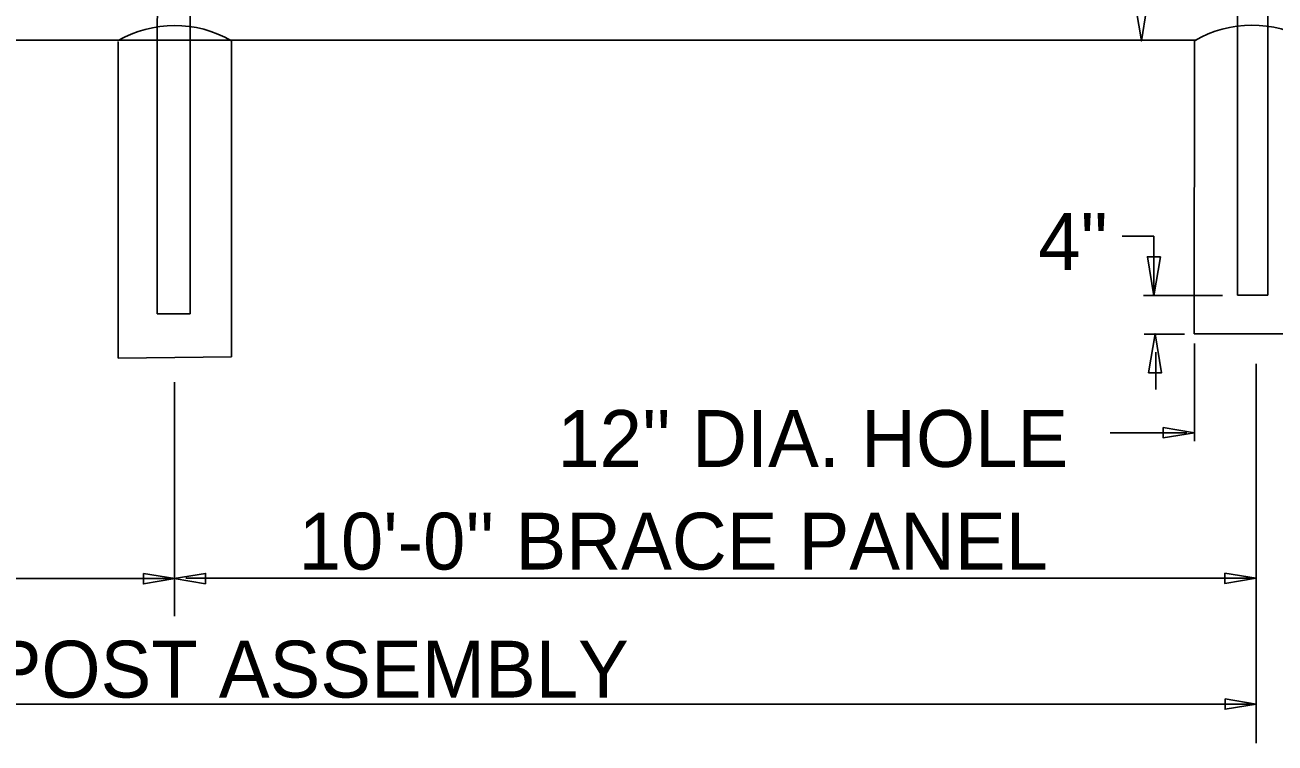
# Model space of a CAD drawing. Extents: x 0 to 2.85, y -0.1 to 1.83.
# Drawn here: x 1.2785 to 1.4984, y 1.158 to 1.2843 of the extents above; entities that cross this region are included whole.
import ezdxf

# ---------------------------------------------------------------- set-up
doc = ezdxf.new("R2010")
doc.units = 0
for name, color, linetype in [('CT_CSHT_GeneralLabel', 7, 'Continuous'), ('CT_Dimensions', 7, 'Continuous'), ('sb_Chainlink Fence', 7, 'Continuous'), ('sb_Earth', 7, 'Continuous'), ('sb_Existing Concrete', 7, 'Continuous'), ('sb_Existing Structural Steel', 7, 'Continuous')]:
    doc.layers.add(name, color=color, linetype=linetype)

msp = doc.modelspace()

# ---------------------------------------------------------------- linework, layer by layer
at = {"layer": 'CT_Dimensions'}
for p, q in [((1.4714931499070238, 1.247114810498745), (1.4771040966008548, 1.247114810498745)), ((1.4771040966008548, 1.2366632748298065), (1.4771040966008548, 1.247114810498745)), ((1.4752588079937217, 1.2366906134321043), (1.4891635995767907, 1.2366906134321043)), ((1.4842187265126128, 1.2110793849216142), (1.4842187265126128, 1.2282577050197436)), ((1.477443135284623, 1.2201522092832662), (1.477443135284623, 1.2267055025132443)), ((1.495061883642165, 1.1579610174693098), (1.495061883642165, 1.2246650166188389)), ((1.3048382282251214, 1.1803051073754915), (1.3048382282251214, 1.2214341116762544)), ((1.4693816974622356, 1.212532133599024), (1.4829063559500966, 1.212532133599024)), ((1.495061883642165, 1.1605798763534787), (1.495061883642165, 1.1919560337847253)), ((1.1104326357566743, 1.1868854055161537), (1.3047967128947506, 1.1868854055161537)), ((1.306856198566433, 1.1869481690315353), (1.495061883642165, 1.1869481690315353)), ((1.1146954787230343, 1.1648183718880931), (1.4947073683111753, 1.1648183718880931))]:
    msp.add_line(p, q, dxfattribs=at)
for points in [[(1.475816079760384, 1.287000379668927), (1.4748999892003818, 1.2815038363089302), (1.4739838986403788, 1.287000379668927)], [(1.4782458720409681, 1.2435038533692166), (1.4771026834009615, 1.2366447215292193), (1.4759594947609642, 1.2435038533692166)], [(1.4761670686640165, 1.2231094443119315), (1.4773102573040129, 1.2299685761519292), (1.4784534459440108, 1.2231094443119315)], [(1.478747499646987, 1.2134659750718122), (1.4842440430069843, 1.2125498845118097), (1.478747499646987, 1.2116337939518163)], [(1.299374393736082, 1.1877955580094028), (1.3048709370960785, 1.1868794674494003), (1.299374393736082, 1.1859633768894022)], [(1.310293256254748, 1.1859693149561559), (1.3047967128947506, 1.1868854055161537), (1.310293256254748, 1.1878014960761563)], [(1.4895653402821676, 1.1878642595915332), (1.495061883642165, 1.1869481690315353), (1.4895653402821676, 1.1860320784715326)], [(1.4896019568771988, 1.165729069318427), (1.4950985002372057, 1.1648129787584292), (1.4896019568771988, 1.1638968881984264)]]:
    msp.add_lwpolyline(points, close=True, dxfattribs=at)
at = {"layer": 'sb_Chainlink Fence'}
msp.add_line((1.4753727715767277, 1.2299105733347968), (1.4824619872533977, 1.2299105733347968), dxfattribs=at)
at = {"layer": 'sb_Earth'}
msp.add_line((1.069795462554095, 1.2815869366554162), (1.4846110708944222, 1.2816125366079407), dxfattribs=at)
at = {"layer": 'sb_Existing Concrete'}
for p, q in [((1.294941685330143, 1.2256677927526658), (1.294941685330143, 1.2813444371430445)), ((1.3148422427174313, 1.225900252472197), (1.3148422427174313, 1.2815358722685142)), ((1.4842025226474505, 1.2299639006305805), (1.4842122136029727, 1.2815267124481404)), ((1.5044127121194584, 1.2299639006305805), (1.4842025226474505, 1.2299639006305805)), ((1.294941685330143, 1.2256677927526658), (1.3148422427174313, 1.225900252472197))]:
    msp.add_line(p, q, dxfattribs=at)
for centre, radius, start, end in [((1.3048514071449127, 1.264117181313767), 0.020080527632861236, 60.16271842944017, 119.89733231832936), ((1.494372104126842, 1.2639625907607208), 0.020290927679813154, 60.31243611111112, 120.04705000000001)]:
    msp.add_arc(centre, radius, start, end, dxfattribs=at)
at = {"layer": 'sb_Existing Structural Steel'}
for p, q in [((1.4917799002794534, 1.2840836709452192), (1.4917799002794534, 1.4119727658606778)), ((1.4971228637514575, 1.284065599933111), (1.4971228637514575, 1.4119727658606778)), ((1.307590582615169, 1.2816417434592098), (1.3072051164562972, 1.4048337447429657)), ((1.3018068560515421, 1.2816824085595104), (1.3020257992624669, 1.4048118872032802)), ((1.4917799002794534, 1.2367549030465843), (1.4917799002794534, 1.284076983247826)), ((1.4971228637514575, 1.2367549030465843), (1.4971228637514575, 1.284076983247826)), ((1.3018068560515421, 1.233457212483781), (1.3018068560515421, 1.2816824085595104)), ((1.307590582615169, 1.2334763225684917), (1.307590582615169, 1.2816417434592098)), ((1.4971228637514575, 1.2367549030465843), (1.4917799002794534, 1.2367549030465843)), ((1.3018068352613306, 1.233463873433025), (1.307584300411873, 1.233463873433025)), ((1.495061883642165, 1.1839804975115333), (1.495061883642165, 1.192143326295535))]:
    msp.add_line(p, q, dxfattribs=at)

# ---------------------------------------------------------------- texts
at = {"layer": 'CT_CSHT_GeneralLabel'}
msp.add_text('CORNER POST ASSEMBLY', height=0.01, dxfattribs=at).set_placement((1.2108514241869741, 1.1659598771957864))
at = {"layer": 'CT_Dimensions'}
for s, p in [('4"', (1.4567756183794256, 1.2412142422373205)), ("12'' DIA. HOLE", (1.3721776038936, 1.2065417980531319)), ("10'-0'' BRACE PANEL", (1.326674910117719, 1.1884823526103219))]:
    msp.add_text(s, height=0.01, dxfattribs=at).set_placement(p)

doc.saveas('drawing.dxf')
